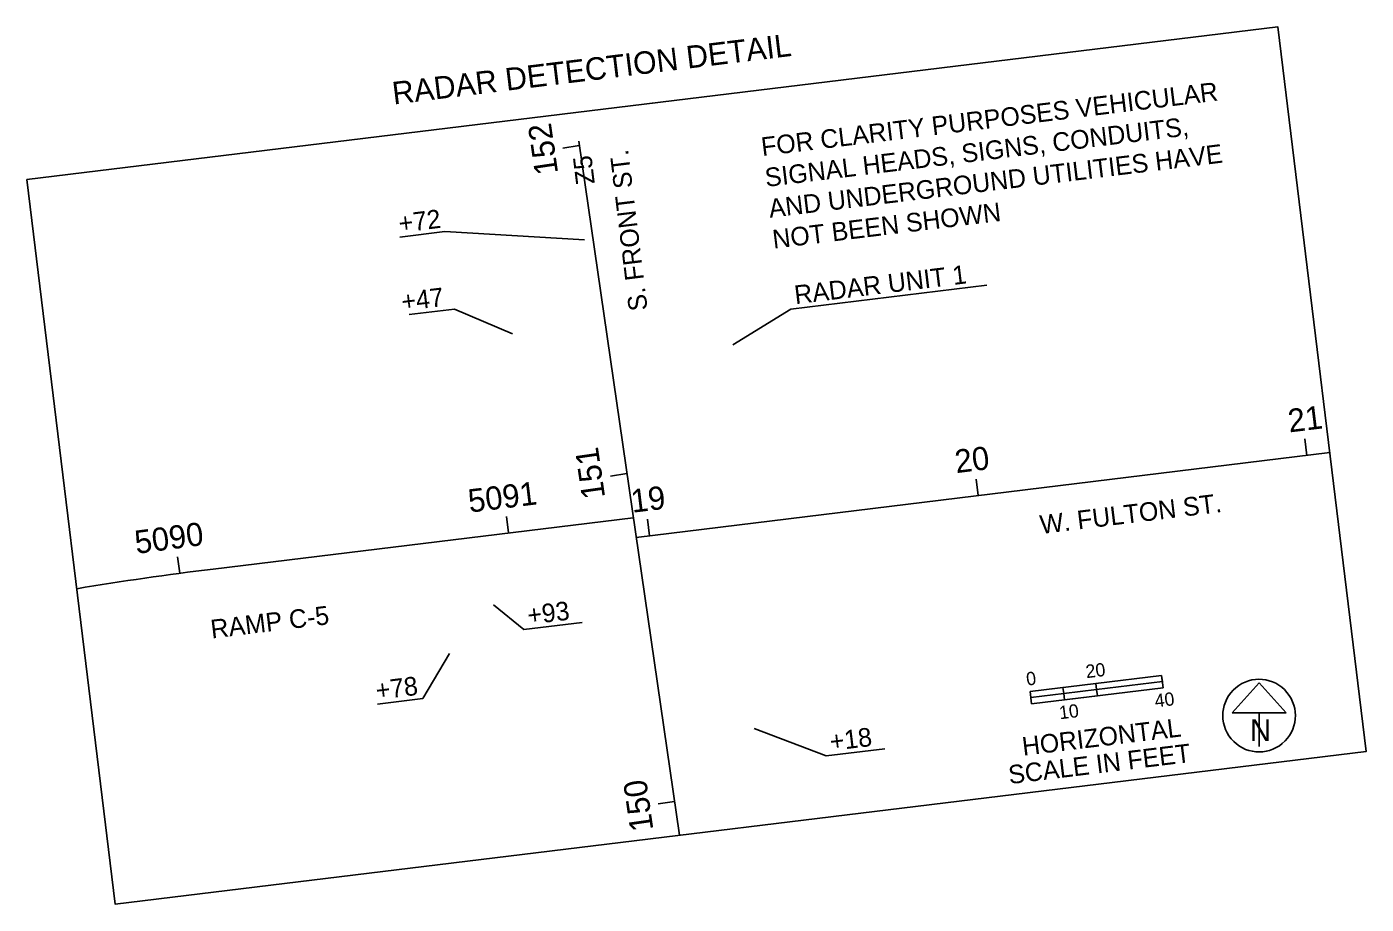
# Model space of a CAD drawing. Extents: x 91401 to 1830080, y 35587 to 712188.
# Drawn here: x 1829675.4 to 1830079.9, y 711922.8 to 712187.6 of the extents above; entities that cross this region are included whole.
import ezdxf

# ---------------------------------------------------------------- set-up
doc = ezdxf.new("R2010")
doc.units = 0
for name, color, linetype in [('GE_P_CL_50', 7, 'Continuous'), ('SG_P_Text', 7, 'Continuous'), ('SH_Data', 7, 'Continuous'), ('SH_Text', 7, 'Continuous')]:
    doc.layers.add(name, color=color, linetype=linetype)

msp = doc.modelspace()

# ---------------------------------------------------------------- linework, layer by layer
at = {"layer": 'GE_P_CL_50'}
for p, q in [((1829872.47, 711943.63), (1829842.07, 712153.06)), ((1829842.26, 712151.71), (1829837.32, 712151)), ((1830061.96, 712058.25), (1830061.36, 712063.21)), ((1829859.42, 712033.52), (1830068.85, 712059.09)), ((1829856.63, 712052.75), (1829851.68, 712052.03)), ((1829962.7, 712046.13), (1829962.09, 712051.09)), ((1829731.68, 712023.97), (1829858.56, 712039.46)), ((1829820.9, 712034.86), (1829820.29, 712039.82)), ((1829863.44, 712034.01), (1829862.83, 712038.97)), ((1829721.64, 712022.69), (1829720.98, 712027.64)), ((1829871, 711953.79), (1829866.05, 711953.07))]:
    msp.add_line(p, q, dxfattribs=at)
msp.add_arc((1829847.42, 711076.08), 954.93, 96.96142, 99.45729, dxfattribs=at)
at = {"layer": 'SH_Data'}
for p, q in [((1829978.37, 711987.02), (1830018.07, 711991.87)), ((1829998.22, 711989.45), (1830018.07, 711991.87)), ((1830018.53, 711988.15), (1830018.07, 711991.87)), ((1830018.07, 711991.87), (1830018.3, 711990.02)), ((1829988.3, 711988.23), (1829978.37, 711987.02)), ((1829978.82, 711983.3), (1829978.37, 711987.02)), ((1829978.37, 711987.02), (1829978.6, 711985.17)), ((1830018.53, 711988.15), (1829978.82, 711983.3)), ((1829988.52, 711986.38), (1829988.3, 711988.23)), ((1829998.45, 711987.59), (1829988.52, 711986.38)), ((1829998.45, 711987.58), (1829998.22, 711989.45)), ((1830018.3, 711990), (1829998.45, 711987.58)), ((1829998.67, 711985.74), (1829998.45, 711987.59)), ((1830018.3, 711990.02), (1830018.3, 711990)), ((1830047.51, 711989.62), (1830039.38, 711980.6)), ((1830055.64, 711980.6), (1830047.51, 711989.62)), ((1829978.6, 711985.17), (1829988.52, 711986.38)), ((1829988.52, 711986.38), (1829988.75, 711984.53)), ((1829988.75, 711984.53), (1829998.67, 711985.74)), ((1830039.38, 711980.6), (1830055.64, 711980.6)), ((1830047.51, 711980.6), (1830047.51, 711970.38))]:
    msp.add_line(p, q, dxfattribs=at)
msp.add_arc((1830047.51, 711979.74), 10.96, 129.7798, 129.7633, dxfattribs=at)
at = {"layer": 'SH_Text'}
msp.add_lwpolyline([(1829675.44, 712141.45), (1830053.16, 712187.57), (1830079.85, 711968.95), (1829702.13, 711922.83)], close=True, dxfattribs=at)
for points in [[(1829843.86, 712123.32), (1829801.68, 712125.78), (1829788.05, 712124.12)], [(1829888.57, 712091.59), (1829906.1, 712102.39), (1829965.26, 712109.61)], [(1829822.06, 712094.89), (1829804.53, 712102.42), (1829790.9, 712100.75)], [(1829816.38, 712013.21), (1829825.48, 712005.71), (1829843.15, 712007.87)], [(1829803.04, 711998.43), (1829794.98, 711984.89), (1829781.35, 711983.22)], [(1829895.02, 711975.85), (1829916.79, 711967.61), (1829934.46, 711969.76)]]:
    msp.add_lwpolyline(points, dxfattribs=at)

# ---------------------------------------------------------------- texts
at = {"layer": 'GE_P_CL_50'}
for s, rotation, p in [('152', 98.2605, (1829835.89, 712143.41)), ('21', 6.9614, (1830056.65, 712065.16)), ('151', 98.2605, (1829850.09, 712045.6)), ('20', 6.9614, (1829956.07, 712052.88)), ('5091', 6.9614, (1829809.13, 712040.98)), ('19', 6.9614, (1829858.26, 712040.93)), ('5090', 7.5685, (1829708.5, 712028.51)), ('150', 98.2605, (1829864.65, 711945.32))]:
    msp.add_text(s, height=7, rotation=rotation, dxfattribs=at).set_placement(p)
at = {"layer": 'SG_P_Text'}
for s, height, rotation, p in [('RADAR DETECTION DETAIL', 6.8, 6.9614, (1829786.21, 712164.1)), ('FOR CLARITY PURPOSES VEHICULAR ', 5.628, 6.9494, (1829897.53, 712148.55)), ('SIGNAL HEADS, SIGNS, CONDUITS, ', 5.628, 6.9494, (1829898.66, 712139.24)), ('Z5', 5.628, 96.9583, (1829846.95, 712140.3)), ('S. FRONT ST.', 5.628, 96.9646, (1829862.9, 712102.2)), ('AND UNDERGROUND UTILITIES HAVE ', 5.628, 6.9494, (1829899.8, 712129.93)), ('+72', 5.628, 6.9583, (1829788.04, 712125.41)), ('NOT BEEN SHOWN', 5.628, 6.9494, (1829900.93, 712120.62)), ('RADAR UNIT 1', 5.628, 6.9646, (1829907.54, 712103.85)), ('+47', 5.628, 6.9583, (1829788.91, 712101.8)), ('W. FULTON ST.', 5.628, 6.9646, (1829981.7, 712034.52)), ('RAMP C-5', 5.628, 6.9646, (1829731.29, 712002.98)), ('+93', 5.628, 6.9646, (1829826.91, 712007.17)), ('+78', 5.628, 6.9583, (1829781.12, 711984.49)), ('+18', 5.628, 6.9646, (1829918.22, 711969.07))]:
    msp.add_text(s, height=height, rotation=rotation, dxfattribs=at).set_placement(p)
at = {"layer": 'SH_Data'}
for s, height, rotation, p in [('20', 4, 6.9614, (1829995.39, 711991.02)), ('0', 4, 6.9614, (1829977.44, 711988.77)), ('40', 4, 6.9614, (1830016.23, 711982.18)), ('10', 4, 6.9614, (1829987.36, 711978.61)), ('HORIZONTAL', 5.6, 6.9614, (1829976.3, 711967.61)), ('N', 6.61, 0, (1830044.75, 711972.04)), ('SCALE IN FEET', 5.6, 6.9614, (1829972.17, 711959.05))]:
    msp.add_text(s, height=height, rotation=rotation, dxfattribs=at).set_placement(p)

doc.saveas('drawing.dxf')
